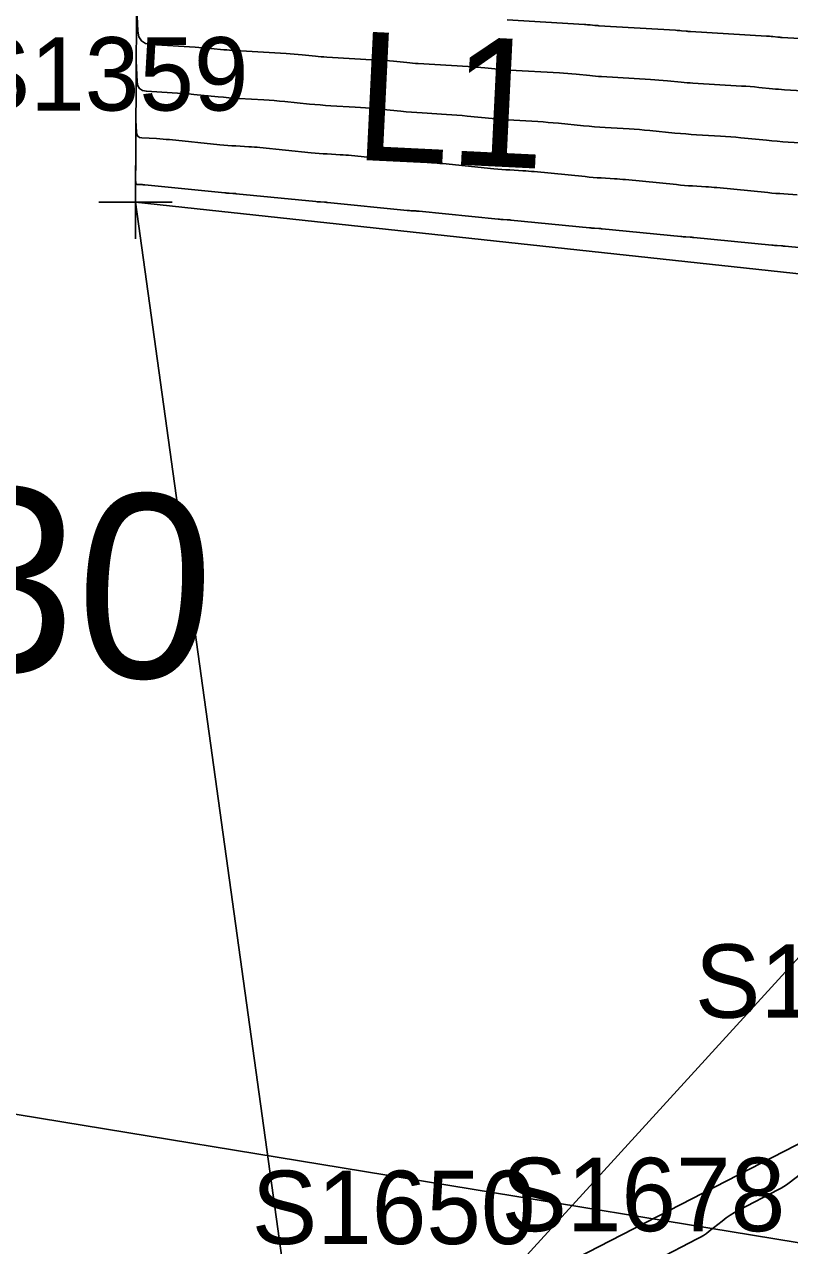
# Model space of a CAD drawing. Extents: x 816928 to 825690, y 436959 to 448212.
# Drawn here: x 818704.4 to 818746.1, y 445127 to 445193.6 of the extents above; entities that cross this region are included whole.
import ezdxf

# ---------------------------------------------------------------- set-up
doc = ezdxf.new("R2010")
doc.units = 0
for name, color, linetype in [('DESIGN - SCRATCH - User 1', 7, 'Continuous'), ('SURVEY - CONTOURS - Index with Text', 7, 'Continuous'), ('SURVEY - CONTOURS - Intermediate with optional Text', 7, 'Continuous'), ('SURVEY - DRAINAGE - Bridge Hydraulic Data - Points - Locators', 7, 'Continuous'), ('SURVEY - DRAINAGE - Bridge Hydraulic Data - Points - Numbers', 7, 'Continuous'), ('SURVEY - DRAINAGE - Bridge Hydraulic Data with Text', 7, 'Continuous'), ('SURVEY - DTM - Breaklines - Points - Numbers', 7, 'Continuous'), ('SURVEY - NON-TRANSPORTATION - Features', 7, 'Continuous'), ('SURVEY - PROPERTY - Parcels', 7, 'Continuous'), ('SURVEY - PROPERTY - Property Lines', 7, 'Continuous')]:
    doc.layers.add(name, color=color, linetype=linetype)

msp = doc.modelspace()

# ---------------------------------------------------------------- linework, layer by layer
at = {"layer": 'DESIGN - SCRATCH - User 1'}
msp.add_lwpolyline([(818977.048, 445516.063), (818962.977, 445468.048), (818911.357, 445419.447), (818895.02, 445347.602), (818900.539, 445320.739), (818847.351, 445272.301), (818844.312, 445271.58), (818842.262, 445267.021), (818783.743, 445227.107), (818781.632, 445226.923), (818713.653, 445215.711), (818710.566, 445206.148), (818710.514, 445201.057), (818710.411, 445183.877), (818720.129, 445113.759), (818716.658, 445105.767), (818715.423, 445100.924), (818715.142, 445099.822), (818745.74, 445051.115)], dxfattribs=at)
at = {"layer": 'SURVEY - CONTOURS - Index with Text'}
msp.add_lwpolyline([(818730.667, 445193.818), (818734.891, 445193.568), (818734.967, 445193.563), (818735.044, 445193.557), (818735.121, 445193.551), (818735.198, 445193.544), (818735.448, 445193.519), (818735.502, 445193.514), (818735.556, 445193.509), (818735.609, 445193.505), (818735.663, 445193.502), (818739.849, 445193.253), (818739.929, 445193.248), (818740.01, 445193.242), (818740.091, 445193.235), (818740.171, 445193.228), (818740.434, 445193.202), (818740.49, 445193.196), (818740.546, 445193.192), (818740.603, 445193.187), (818740.659, 445193.184), (818744.807, 445192.937), (818744.892, 445192.931), (818744.976, 445192.925), (818745.06, 445192.918), (818745.144, 445192.91), (818745.419, 445192.883), (818745.478, 445192.877), (818745.537, 445192.872), (818745.596, 445192.868), (818745.655, 445192.864), (818749.766, 445192.618)], dxfattribs=at)
at = {"layer": 'SURVEY - CONTOURS - Intermediate with optional Text'}
for points in [[(818710.476, 445194.823), (818710.541, 445193.205), (818710.596, 445192.899), (818710.735, 445192.675), (818710.956, 445192.533), (818711.261, 445192.472), (818713.66, 445192.332), (818713.877, 445192.319), (818714.095, 445192.303), (818714.312, 445192.284), (818714.529, 445192.264), (818715.239, 445192.193), (818715.391, 445192.179), (818715.543, 445192.166), (818715.695, 445192.155), (818715.847, 445192.145), (818718.624, 445191.983), (818718.845, 445191.969), (818719.065, 445191.953), (818719.285, 445191.934), (818719.505, 445191.913), (818720.222, 445191.842), (818720.376, 445191.827), (818720.53, 445191.814), (818720.684, 445191.803), (818720.838, 445191.793), (818723.59, 445191.632), (818723.812, 445191.618), (818724.035, 445191.601), (818724.258, 445191.583), (818724.48, 445191.562), (818725.206, 445191.489), (818725.361, 445191.475), (818725.517, 445191.462), (818725.673, 445191.45), (818725.829, 445191.44), (818728.555, 445191.28), (818728.78, 445191.265), (818729.005, 445191.248), (818729.23, 445191.23), (818729.455, 445191.208), (818730.189, 445191.135), (818730.347, 445191.121), (818730.504, 445191.107), (818730.662, 445191.096), (818730.819, 445191.086), (818733.521, 445190.926), (818733.748, 445190.911), (818733.976, 445190.894), (818734.203, 445190.875), (818734.431, 445190.854), (818735.173, 445190.78), (818735.332, 445190.765), (818735.491, 445190.752), (818735.65, 445190.74), (818735.81, 445190.73), (818738.486, 445190.571), (818738.717, 445190.556), (818738.947, 445190.539), (818739.176, 445190.52), (818739.406, 445190.498), (818740.156, 445190.424), (818740.317, 445190.409), (818740.478, 445190.395), (818740.639, 445190.383), (818740.8, 445190.373), (818743.453, 445190.215), (818743.685, 445190.2), (818743.917, 445190.182), (818744.15, 445190.163), (818744.382, 445190.141), (818745.139, 445190.066), (818745.302, 445190.051), (818745.464, 445190.037), (818745.627, 445190.025), (818745.789, 445190.014), (818748.419, 445189.857)], [(818710.457, 445191.588), (818710.502, 445190.449), (818710.541, 445190.233), (818710.639, 445190.075), (818710.795, 445189.975), (818711.01, 445189.932), (818712.407, 445189.851), (818712.707, 445189.832), (818713.006, 445189.81), (818713.305, 445189.785), (818713.604, 445189.756), (818714.928, 445189.624), (818715.212, 445189.598), (818715.496, 445189.574), (818715.78, 445189.553), (818716.065, 445189.535), (818717.407, 445189.456), (818717.694, 445189.438), (818717.981, 445189.417), (818718.268, 445189.393), (818718.555, 445189.366), (818719.901, 445189.231), (818720.19, 445189.204), (818720.478, 445189.18), (818720.767, 445189.159), (818721.057, 445189.14), (818722.387, 445189.062), (818722.672, 445189.044), (818722.957, 445189.023), (818723.241, 445188.999), (818723.526, 445188.972), (818724.88, 445188.837), (818725.17, 445188.81), (818725.461, 445188.786), (818725.752, 445188.764), (818726.043, 445188.745), (818727.366, 445188.668), (818727.649, 445188.649), (818727.932, 445188.628), (818728.215, 445188.605), (818728.498, 445188.578), (818729.86, 445188.443), (818730.152, 445188.415), (818730.444, 445188.391), (818730.736, 445188.369), (818731.029, 445188.35), (818732.344, 445188.272), (818732.626, 445188.254), (818732.908, 445188.233), (818733.189, 445188.21), (818733.47, 445188.183), (818734.839, 445188.047), (818735.133, 445188.02), (818735.426, 445187.995), (818735.72, 445187.973), (818736.014, 445187.954), (818737.323, 445187.877), (818737.603, 445187.859), (818737.883, 445187.838), (818738.163, 445187.814), (818738.443, 445187.788), (818739.819, 445187.652), (818740.114, 445187.624), (818740.409, 445187.599), (818740.704, 445187.577), (818741, 445187.558), (818742.302, 445187.48), (818742.58, 445187.462), (818742.859, 445187.442), (818743.138, 445187.418), (818743.416, 445187.392), (818744.798, 445187.255), (818745.094, 445187.227), (818745.391, 445187.202), (818745.688, 445187.18), (818745.985, 445187.161), (818747.28, 445187.084)], [(818710.438, 445188.354), (818710.464, 445187.692), (818710.487, 445187.567), (818710.543, 445187.476), (818710.634, 445187.417), (818710.759, 445187.392), (818711.57, 445187.345), (818711.744, 445187.334), (818711.918, 445187.321), (818712.091, 445187.307), (818712.264, 445187.29), (818715.014, 445187.016), (818715.231, 445186.996), (818715.448, 445186.977), (818715.666, 445186.961), (818715.883, 445186.947), (818716.594, 445186.906), (818716.746, 445186.896), (818716.898, 445186.885), (818717.05, 445186.872), (818717.202, 445186.858), (818719.992, 445186.58), (818720.209, 445186.56), (818720.427, 445186.541), (818720.644, 445186.525), (818720.862, 445186.511), (818721.574, 445186.47), (818721.726, 445186.46), (818721.879, 445186.449), (818722.031, 445186.436), (818722.183, 445186.421), (818724.969, 445186.144), (818725.187, 445186.124), (818725.405, 445186.105), (818725.623, 445186.089), (818725.841, 445186.075), (818726.554, 445186.033), (818726.707, 445186.024), (818726.859, 445186.012), (818727.012, 445185.999), (818727.164, 445185.985), (818729.947, 445185.709), (818730.165, 445185.688), (818730.383, 445185.67), (818730.601, 445185.653), (818730.82, 445185.639), (818731.534, 445185.597), (818731.687, 445185.587), (818731.84, 445185.576), (818731.993, 445185.563), (818732.145, 445185.549), (818734.924, 445185.273), (818735.143, 445185.253), (818735.361, 445185.234), (818735.58, 445185.218), (818735.799, 445185.204), (818736.514, 445185.161), (818736.667, 445185.151), (818736.82, 445185.14), (818736.973, 445185.127), (818737.126, 445185.113), (818739.902, 445184.838), (818740.121, 445184.817), (818740.339, 445184.799), (818740.559, 445184.782), (818740.778, 445184.768), (818741.494, 445184.726), (818741.648, 445184.716), (818741.801, 445184.704), (818741.954, 445184.691), (818742.107, 445184.677), (818744.879, 445184.403), (818745.099, 445184.382), (818745.318, 445184.364), (818745.537, 445184.347), (818745.757, 445184.333), (818746.474, 445184.29)], [(818710.418, 445185.12), (818710.426, 445184.936), (818710.432, 445184.901), (818710.448, 445184.876), (818710.473, 445184.86), (818710.507, 445184.853), (818710.733, 445184.84), (818710.781, 445184.837), (818710.829, 445184.833), (818710.877, 445184.829), (818710.925, 445184.824), (818715.277, 445184.39), (818715.339, 445184.384), (818715.401, 445184.379), (818715.463, 445184.375), (818715.525, 445184.371), (818715.728, 445184.359), (818715.772, 445184.356), (818715.815, 445184.353), (818715.858, 445184.349), (818715.902, 445184.345), (818720.247, 445183.912), (818720.311, 445183.906), (818720.375, 445183.901), (818720.438, 445183.896), (818720.502, 445183.892), (818720.711, 445183.88), (818720.756, 445183.877), (818720.801, 445183.874), (818720.845, 445183.87), (818720.89, 445183.866), (818725.217, 445183.435), (818725.283, 445183.429), (818725.348, 445183.424), (818725.414, 445183.419), (818725.48, 445183.415), (818725.695, 445183.402), (818725.741, 445183.399), (818725.786, 445183.396), (818725.832, 445183.392), (818725.878, 445183.387), (818730.187, 445182.959), (818730.255, 445182.953), (818730.322, 445182.947), (818730.39, 445182.942), (818730.457, 445182.938), (818730.678, 445182.925), (818730.725, 445182.922), (818730.772, 445182.918), (818730.819, 445182.914), (818730.866, 445182.91), (818735.158, 445182.484), (818735.227, 445182.478), (818735.296, 445182.472), (818735.365, 445182.467), (818735.434, 445182.462), (818735.661, 445182.449), (818735.709, 445182.446), (818735.758, 445182.442), (818735.806, 445182.438), (818735.854, 445182.433), (818740.129, 445182.01), (818740.199, 445182.003), (818740.27, 445181.997), (818740.341, 445181.992), (818740.412, 445181.987), (818740.644, 445181.974), (818740.693, 445181.97), (818740.743, 445181.967), (818740.792, 445181.962), (818740.842, 445181.958), (818745.099, 445181.536), (818745.172, 445181.53), (818745.244, 445181.523), (818745.317, 445181.518), (818745.389, 445181.513), (818745.627, 445181.499), (818745.677, 445181.496), (818745.728, 445181.492), (818745.779, 445181.488), (818745.83, 445181.483), (818750.07, 445181.064)], [(818746.662, 445130.892), (818746.035, 445130.416), (818745.899, 445130.317), (818745.758, 445130.225), (818745.614, 445130.138), (818745.466, 445130.057), (818743.306, 445128.94), (818743.065, 445128.807), (818742.832, 445128.664), (818742.605, 445128.509), (818742.386, 445128.344), (818741.681, 445127.784), (818741.528, 445127.668), (818741.369, 445127.559), (818741.205, 445127.459), (818741.037, 445127.366), (818738.866, 445126.241)]]:
    msp.add_lwpolyline(points, dxfattribs=at)
at = {"layer": 'SURVEY - DRAINAGE - Bridge Hydraulic Data - Points - Locators'}
for p, q in [((818710.411, 445185.877), (818710.411, 445181.877)), ((818712.411, 445183.877), (818708.411, 445183.877))]:
    msp.add_line(p, q, dxfattribs=at)
at = {"layer": 'SURVEY - DRAINAGE - Bridge Hydraulic Data with Text'}
msp.add_line((818710.411, 445183.877), (818757.852, 445178.757), dxfattribs=at)
msp.add_lwpolyline([(818757.852, 445178.757), (818763.137, 445177.424), (818765.335, 445176.778), (818763.85, 445174.738), (818755.626, 445156.7), (818750.208, 445134.422), (818726.213, 445122.086), (818716.658, 445105.767), (818715.142, 445099.822), (818717.206, 445098.8), (818722.312, 445098.543), (818727.161, 445104.474), (818730.225, 445110.91), (818749.677, 445108.675), (818763.087, 445111.464), (818772.094, 445127.037), (818775.326, 445153.725), (818783.56, 445177.129), (818784.519, 445183.127)], dxfattribs=at)
at = {"layer": 'SURVEY - NON-TRANSPORTATION - Features'}
msp.add_lwpolyline([(818878.723, 445102.028), (818832.174, 445159.68), (818783.535, 445180.107), (818767.737, 445165.919), (818720.129, 445113.759)], dxfattribs=at)
at = {"layer": 'SURVEY - PROPERTY - Parcels'}
for p, q in [((817997.463, 445250.198), (818815.75, 445115.787)), ((818815.75, 445115.787), (817997.463, 445250.198))]:
    msp.add_line(p, q, dxfattribs=at)
at = {"layer": 'SURVEY - PROPERTY - Property Lines'}
msp.add_line((817997.463, 445250.198), (818815.75, 445115.787), dxfattribs=at)

# ---------------------------------------------------------------- texts
at = {"layer": 'SURVEY - DRAINAGE - Bridge Hydraulic Data - Points - Numbers'}
for s, p in [('S1359', (818701.107, 445188.877)), ('S1649', (818740.905, 445139.422)), ('S1650', (818716.752, 445127.086))]:
    msp.add_text(s, height=4, dxfattribs=at).set_placement(p)
at = {"layer": 'SURVEY - DRAINAGE - Bridge Hydraulic Data with Text'}
for s, height, rotation, p in [('L1', 7, 357.19314, (818722.246, 445186.208)), ('30', 10, 357.36718, (818699.565, 445158.476))]:
    msp.add_text(s, height=height, rotation=rotation, dxfattribs=at).set_placement(p)
at = {"layer": 'SURVEY - DTM - Breaklines - Points - Numbers'}
msp.add_text('S1678', height=4, dxfattribs=at).set_placement((818730.36, 445127.788))

doc.saveas('drawing.dxf')
